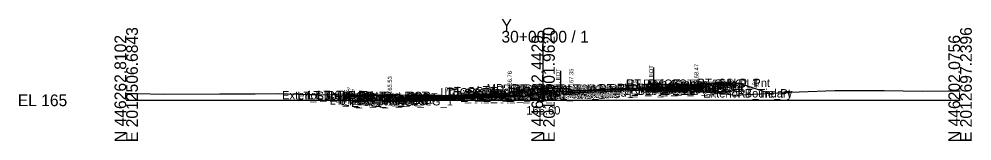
# Model space of a CAD drawing. Extents: x -26 to 3203, y -10 to 9532.
# Drawn here: x 1974.3 to 2202.8, y 3990.3 to 4019.4 of the extents above; entities that cross this region are included whole.
import ezdxf

# ---------------------------------------------------------------- set-up
doc = ezdxf.new("R2010")
doc.units = 0
for name, color, linetype in [('Default', 7, 'Continuous'), ('Exist CMT Pavement', 7, 'Continuous'), ('Exist Cross Section Cell', 7, 'Continuous'), ('Exist XS Center Line Elevation Label', 7, 'Continuous'), ('Exist XS Ground Line', 7, 'Continuous'), ('Prop CMT Conc Surface', 7, 'Continuous'), ('Prop CMT Concrete Structures', 7, 'Continuous'), ('Prop CMT Pvmt Course 1', 7, 'Continuous'), ('Prop CMT Pvmt Course 1 CG', 7, 'Continuous'), ('Prop CMT Pvmt Course 2', 7, 'Continuous'), ('Prop CMT Pvmt Course 2 Wedge', 7, 'Continuous'), ('Prop CMT Pvmt Course 3', 7, 'Continuous'), ('Prop CMT Pvmt Surface', 7, 'Continuous'), ('Prop CMT Pvmt Wedge Surface 2', 7, 'Continuous'), ('Prop CMT Pvmt Wedge Surface 3', 7, 'Continuous'), ('Prop CMT Slope Grass', 7, 'Continuous'), ('Prop CMT Subgrade Earthwork', 7, 'Continuous'), ('Prop XS Hydro Elevations', 7, 'Continuous'), ('Prop XS Label Text', 7, 'Continuous'), ('Prop XS SE Text', 7, 'Continuous'), ('Prop XS Side Slope Text', 7, 'Continuous'), ('Scratch_Level_0', 7, 'Continuous')]:
    doc.layers.add(name, color=color, linetype=linetype)

msp = doc.modelspace()

# ---------------------------------------------------------------- linework, layer by layer
at = {"layer": 'Exist CMT Pavement'}
msp.add_lwpolyline([(2104.17, 4002.07), (2104.17, 4002.07), (2105.31, 4002.11), (2105.93, 4002.14), (2107.94, 4002.25), (2109.92, 4002.32), (2110.57, 4002.34), (2111.82, 4002.38), (2113.18, 4002.43), (2114.04, 4002.47), (2115.35, 4002.53), (2116.08, 4002.56), (2118.4, 4002.63), (2119.51, 4002.66), (2121.03, 4002.71), (2121.82, 4002.73), (2123.64, 4002.76), (2124.34, 4002.78), (2126.48, 4002.84)], dxfattribs=at)
at = {"layer": 'Exist Cross Section Cell'}
for p, q in [((2100, 4000), (2100, 4016.6)), ((2000, 4000), (2100, 4000)), ((2100, 4000), (2200, 4000))]:
    msp.add_line(p, q, dxfattribs=at)
at = {"layer": 'Exist XS Ground Line'}
msp.add_lwpolyline([(2000, 4001.6), (2001.67, 4001.6), (2002.73, 4001.6), (2008.89, 4001.5), (2022.47, 4001.56), (2030.9, 4001.57), (2036.45, 4001.59), (2043.97, 4001.38), (2044.41, 4001.37), (2045.8, 4001.35), (2054.46, 4001.26), (2060.33, 4001.29), (2068.43, 4001.25), (2075.69, 4001.19), (2084.09, 4000.7), (2084.44, 4000.69), (2085.79, 4000.73), (2095.79, 4001.08), (2100, 4001.6), (2101.16, 4001.75), (2102.89, 4001.99), (2103.78, 4002.05), (2104.17, 4002.07), (2105.31, 4002.11), (2105.93, 4002.14), (2107.94, 4002.25), (2109.92, 4002.32), (2110.57, 4002.34), (2111.82, 4002.38), (2113.18, 4002.43), (2114.04, 4002.47), (2115.35, 4002.53), (2116.08, 4002.56), (2118.4, 4002.63), (2119.51, 4002.66), (2121.03, 4002.71), (2121.82, 4002.73), (2123.64, 4002.76), (2124.34, 4002.78), (2126.48, 4002.84), (2127.28, 4002.85), (2127.86, 4002.85), (2128.41, 4002.86), (2130.68, 4002.66), (2134.09, 4002.36), (2136.67, 4002.21), (2143.29, 4001.62), (2145.82, 4001.19), (2155.27, 4001.74), (2157.84, 4001.85), (2161.4, 4001.99), (2169.93, 4002.34), (2177.54, 4002.38), (2180.43, 4002.38), (2181.78, 4002.36), (2190.92, 4002.15), (2197.19, 4002.24), (2200, 4002.29)], dxfattribs=at)
at = {"layer": 'Prop CMT Conc Surface'}
for points in [[(2136.75, 4003.47), (2136.75, 4003.97), (2137.25, 4003.97)], [(2141.25, 4004.06), (2146.25, 4004.16)], [(2091.25, 4001.73), (2092, 4001.76), (2092, 4001.93), (2092.76, 4002.18)], [(2108.75, 4002.43), (2106.75, 4002.35), (2106.75, 4002.52), (2106, 4002.77)], [(2134.75, 4003.47), (2136.75, 4003.47)], [(2058.75, 4001.12), (2053.75, 4001.22)], [(2063.25, 4000.53), (2063.25, 4001.03), (2062.75, 4001.03)], [(2065.25, 4000.69), (2063.25, 4000.53)]]:
    msp.add_lwpolyline(points, dxfattribs=at)
at = {"layer": 'Prop CMT Concrete Structures'}
for points in [[(2134.75, 4003.47), (2136.75, 4003.47), (2136.75, 4003.97), (2137.25, 4003.97)], [(2137.25, 4003.97), (2137.25, 4002.99), (2134.75, 4002.89)], [(2146.25, 4004.16), (2141.25, 4004.06)], [(2141.25, 4004.06), (2141.25, 4003.73)], [(2146.25, 4003.83), (2146.25, 4004.16)], [(2091.25, 4001.73), (2092, 4001.76), (2092, 4001.93), (2092.76, 4002.18)], [(2091.25, 4001.15), (2091.25, 4001.73)], [(2092.76, 4002.18), (2092.76, 4001.21)], [(2108.75, 4002.43), (2106.75, 4002.35), (2106.75, 4002.52), (2106, 4002.77)], [(2106, 4002.77), (2106, 4001.74)], [(2106, 4001.74), (2108.75, 4001.85)], [(2108.75, 4001.85), (2108.75, 4002.43)], [(2134.75, 4002.89), (2134.75, 4003.47)], [(2141.25, 4003.73), (2146.25, 4003.83)], [(2053.75, 4000.89), (2053.75, 4001.22)], [(2053.75, 4001.22), (2058.75, 4001.12)], [(2058.75, 4000.79), (2053.75, 4000.89)], [(2058.75, 4001.12), (2058.75, 4000.79)], [(2065.25, 4000.69), (2063.25, 4000.53), (2063.25, 4001.03), (2062.75, 4001.03)], [(2062.75, 4001.03), (2062.75, 4000.01), (2065.25, 4000.11)], [(2065.25, 4000.11), (2065.25, 4000.69)], [(2092.76, 4001.21), (2091.25, 4001.15)]]:
    msp.add_lwpolyline(points, dxfattribs=at)
at = {"layer": 'Prop CMT Pvmt Course 1'}
for points in [[(2091.25, 4001.73), (2065.25, 4000.69)], [(2091.25, 4001.48), (2091.25, 4001.73)], [(2108.75, 4002.43), (2134.75, 4003.47)], [(2108.75, 4002.18), (2108.75, 4002.43)], [(2108.75, 4002.18), (2108.75, 4002.18)], [(2134.75, 4003.22), (2128.41, 4002.97), (2122.99, 4002.75)], [(2134.75, 4003.47), (2134.75, 4003.22)], [(2065.25, 4000.44), (2091.25, 4001.48)], [(2065.25, 4000.69), (2065.25, 4000.44)], [(2091.25, 4001.48), (2091.25, 4001.48), (2091.25, 4001.48)]]:
    msp.add_lwpolyline(points, dxfattribs=at)
at = {"layer": 'Prop CMT Pvmt Course 1 CG'}
for points in [[(2108.75, 4001.85), (2105.5, 4001.72), (2105.15, 4001.37)], [(2108.75, 4001.52), (2108.75, 4001.85)], [(2134.75, 4002.89), (2137.75, 4003.01), (2138.07, 4002.69)], [(2134.75, 4002.56), (2134.75, 4002.89)], [(2138.07, 4002.69), (2134.75, 4002.56)], [(2065.25, 4000.11), (2062.25, 3999.99), (2061.9, 3999.64)], [(2061.9, 3999.64), (2065.25, 3999.78)], [(2065.25, 3999.78), (2065.25, 4000.11)], [(2091.25, 4001.15), (2093.26, 4001.23), (2093.58, 4000.91)], [(2091.25, 4000.82), (2091.25, 4001.15)], [(2093.58, 4000.91), (2091.25, 4000.82)], [(2105.15, 4001.37), (2108.75, 4001.52)]]:
    msp.add_lwpolyline(points, dxfattribs=at)
at = {"layer": 'Prop CMT Pvmt Course 2'}
msp.add_lwpolyline([(2108.75, 4002.18), (2108.75, 4001.85), (2108.75, 4001.85)], close=True, dxfattribs=at)
for points in [[(2108.75, 4002.18), (2108.75, 4002.18)], [(2126.48, 4002.89), (2134.75, 4003.22)], [(2134.75, 4002.89), (2126.48, 4002.56)], [(2126.48, 4002.56), (2126.48, 4002.89)], [(2134.75, 4003.22), (2134.75, 4002.89)], [(2091.25, 4001.48), (2065.25, 4000.44)], [(2065.25, 4000.11), (2091.25, 4001.15)], [(2065.25, 4000.44), (2065.25, 4000.11)], [(2091.25, 4001.15), (2091.25, 4001.48)]]:
    msp.add_lwpolyline(points, dxfattribs=at)
at = {"layer": 'Prop CMT Pvmt Course 2 Wedge'}
msp.add_lwpolyline([(2122.99, 4002.75), (2126.48, 4002.89)], dxfattribs=at)
at = {"layer": 'Prop CMT Pvmt Course 3'}
for points in [[(2108.75, 4001.85), (2108.75, 4001.85), (2108.75, 4001.52), (2108.75, 4001.52)], [(2108.75, 4001.52), (2108.75, 4001.85)], [(2126.48, 4002.56), (2134.75, 4002.89)], [(2134.75, 4002.56), (2126.48, 4002.22)], [(2126.48, 4002.22), (2126.48, 4002.56)], [(2134.75, 4002.89), (2134.75, 4002.56)], [(2091.25, 4001.15), (2065.25, 4000.11)], [(2065.25, 3999.78), (2091.25, 4000.82)], [(2065.25, 4000.11), (2065.25, 3999.78)], [(2091.25, 4000.82), (2091.25, 4001.15)]]:
    msp.add_lwpolyline(points, dxfattribs=at)
at = {"layer": 'Prop CMT Pvmt Surface'}
for points in [[(2091.25, 4001.73), (2065.25, 4000.69)], [(2108.75, 4002.43), (2134.75, 4003.47)]]:
    msp.add_lwpolyline(points, dxfattribs=at)
at = {"layer": 'Prop CMT Pvmt Wedge Surface 2'}
msp.add_lwpolyline([(2108.75, 4002.18), (2134.75, 4003.22)], dxfattribs=at)
at = {"layer": 'Prop CMT Pvmt Wedge Surface 3'}
msp.add_lwpolyline([(2108.75, 4001.85), (2134.75, 4002.89)], dxfattribs=at)
at = {"layer": 'Prop CMT Slope Grass'}
for points in [[(2137.25, 4003.97), (2146.75, 4004.16)], [(2146.75, 4004.16), (2154.22, 4001.67)], [(2092.76, 4002.18), (2099.38, 4002.9)], [(2106, 4002.77), (2099.38, 4002.9)], [(2053.25, 4001.22), (2053.11, 4001.27)], [(2062.75, 4001.03), (2053.25, 4001.22)]]:
    msp.add_lwpolyline(points, dxfattribs=at)
at = {"layer": 'Prop CMT Subgrade Earthwork'}
for points in [[(2134.75, 4002.56), (2138.07, 4002.69), (2139.4, 4004.02)], [(2095.11, 4002.44), (2093.58, 4000.91)], [(2103.71, 4002.81), (2105.15, 4001.37)], [(2108.75, 4001.52), (2108.74, 4002.27)], [(2126.48, 4002.22), (2126.5, 4002.84)], [(2126.48, 4002.22), (2134.75, 4002.56)], [(2134.75, 4002.56), (2134.75, 4002.56)], [(2065.25, 3999.78), (2061.9, 3999.64), (2060.47, 4001.08)], [(2091.25, 4000.82), (2065.25, 3999.78)], [(2065.25, 3999.78), (2065.25, 3999.78)], [(2093.58, 4000.91), (2091.25, 4000.82)], [(2091.25, 4000.82), (2091.25, 4000.82)], [(2091.25, 4000.82), (2091.25, 4000.82)], [(2105.15, 4001.37), (2108.75, 4001.52)], [(2108.75, 4001.52), (2108.75, 4001.52)], [(2108.75, 4001.52), (2108.75, 4001.52)]]:
    msp.add_lwpolyline(points, dxfattribs=at)
at = {"layer": 'Prop XS Label Text'}
for p, q in [((2104.17, 4007.07), (2104.17, 4002.07)), ((2126.48, 4007.84), (2126.48, 4002.84))]:
    msp.add_line(p, q, dxfattribs=at)

# ---------------------------------------------------------------- texts
at = {"layer": 'Default'}
msp.add_text('-', height=0.0001, dxfattribs=at).set_placement((2000, 4000))
at = {"layer": 'Exist Cross Section Cell'}
for s, p in [('Y', (2090, 4016.6)), ('30+00.00 / 1', (2090, 4013.8)), ('EL 165', (1974, 3998.6))]:
    msp.add_text(s, height=2.8, dxfattribs=at).set_placement(p)
for s, p in [('N 446262.8102', (2000, 3990)), ('E 2012506.6843', (2002.8, 3990)), ('N 446232.4429', (2100, 3990)), ('E 2012601.9620', (2102.8, 3990)), ('N 446202.0756', (2200, 3990)), ('E 2012697.2396', (2202.8, 3990))]:
    msp.add_text(s, height=2.8, rotation=90, dxfattribs=at).set_placement(p)
at = {"layer": 'Exist XS Center Line Elevation Label'}
msp.add_text('166.60', height=2, dxfattribs=at).set_placement((2095.95, 3996.6))
at = {"layer": 'Prop XS Hydro Elevations'}
for s, p in [('168.47', (2137.25, 4004.47)), ('166.76', (2092.5, 4002.76)), ('167.35', (2107.25, 4003.35)), ('165.53', (2063.75, 4001.53))]:
    msp.add_text(s, height=1, rotation=90, dxfattribs=at).set_placement(p)
at = {"layer": 'Prop XS Label Text'}
for p in [(2104.07, 4003.09), (2126.38, 4003.86)]:
    msp.add_text('E. EOT', height=1, rotation=90, dxfattribs=at).set_placement(p)
at = {"layer": 'Prop XS SE Text'}
for p in [(2119.96, 4003.88), (2076.46, 4002.14)]:
    msp.add_text('0.040', height=1, rotation=2.2906, dxfattribs=at).set_placement(p)
at = {"layer": 'Prop XS Side Slope Text'}
for p in [(2149.97, 4003.88), (2052.66, 4002.21)]:
    msp.add_text('3:1', height=1, rotation=341.5651, dxfattribs=at).set_placement(p)
at = {"layer": 'Scratch_Level_0'}
for s, p in [('MD_Crown Point', (2086.45, 4001.9)), ('RT_Sub_DLT_In', (2092.61, 4001.81)), ('RT_PV_Sub_Tie_Out', (2113.32, 4001.86)), ('RT_PV_OEEOP_EG', (2115.91, 4001.86)), ('RT_PV2_OEEOP', (2117.67, 4001.97)), ('RT_Sub_Trench_Out_DLT', (2119.92, 4003.02)), ('RT_CG_Top_Face', (2123.96, 4002.97)), ('RT_CG1_Shelf_Out', (2124.25, 4002.01)), ('RT_CG_Bot_IE', (2124.62, 4001.89)), ('RT_PV2_OEOT', (2124.88, 4002.22)), ('RT_PV3_OEOT', (2124.88, 4001.89)), ('RT_CG_Top_Gut', (2124.94, 4002.47)), ('RT_PV1_OEOT', (2125.44, 4002.47)), ('RT_CG_Top_BOC', (2125.49, 4002.97)), ('RT_CG_Bot_BOC', (2125.52, 4001.99)), ('RT_CSLP_Pnt', (2136.88, 4003.16)), ('Exterior Boundary', (2037.39, 4000.22)), ('LT_Sub_Trench_Out_DLT', (2041.03, 4000.08)), ('LT_CSLP_Pnt', (2043.42, 4000.22)), ('LT_Tie_Pt', (2045.82, 4000.27)), ('LT_CG_Top_Face', (2050.51, 4000.03)), ('LT_CG_Top_BOC', (2051.03, 4000.03)), ('LT_PV1_OEOT', (2055.99, 3999.69)), ('LT_CG_Top_Face_Med', (2075.37, 4000.93)), ('LT_CG_Top_Gut_Med', (2076.35, 4000.76)), ('LT_CG_Top_BOC_Med', (2077.15, 4001.18)), ('LT_CG_Bot_BOC_Med', (2077.19, 4000.21)), ('LT_CG_Bot_IE_Med', (2077.31, 4000.15)), ('LT_Sub_IEOT_CG_1', (2078.12, 3999.82)), ('LT_Sub_OEEOP', (2080.46, 3999.82)), ('LT_PV2_OEEOP', (2080.56, 4000.48)), ('LT_PV3_OEEOP', (2080.56, 4000.15)), ('LT_Sub_IEEOP', (2081.11, 3999.82)), ('LT_PV2_IEEOP', (2081.2, 4000.48)), ('LT_CG1_Shelf_In', (2081.43, 4000.23)), ('LT_Sub_PGL', (2082.37, 3999.82)), ('LT_PV2_PGL', (2082.46, 4000.48)), ('LT_PV1_PGL', (2083.03, 4000.73)), ('LT_Sub_DLT_In', (2084.05, 4001.44)), ('LT_Sub_IEOP', (2084.34, 3999.91)), ('RT_CG_Top_BOC_Med', (2090.35, 4001.77)), ('RT_CG_Bot BOC In', (2091.84, 4000.74)), ('RT_CG_Top_BOC In', (2091.97, 4001.77)), ('RT_CG_Top FOC In', (2092.61, 4001.52)), ('RT_CG_Top_Gut In', (2092.64, 4001.35)), ('RT_CG1_Shelf_In', (2093.63, 4000.72)), ('RT_CG_Bot_IE_Med', (2094.77, 4000.85)), ('RT_PV_Sub_Tie_In', (2095.25, 4001.27)), ('RT_Sub_IEOT_CG_1', (2095.57, 4000.52)), ('RT_Sub_IEOP', (2095.86, 4000.37)), ('RT_PV_IEEOP_EG', (2096.89, 4001.28)), ('RT_Sub_IEEOP', (2098.56, 4000.52)), ('RT_PV2_IEEOP', (2098.66, 4001.18)), ('RT_PV3_IEEOP', (2098.66, 4000.85)), ('RT_Sub_PGL', (2099.82, 4000.52)), ('RT_PV2_PGL', (2099.92, 4001.18)), ('RT_PV3_PGL', (2099.92, 4000.85)), ('RT_PV1_PGL', (2100.48, 4001.43)), ('RT_Sub_OEEOP', (2117.58, 4001.3)), ('RT_PV3_OEEOP', (2117.67, 4001.64)), ('RT_Sub_OEOT_CG_1', (2120.92, 4001.56)), ('RT_Sub_OEOT', (2124.78, 4001.56)), ('RT_Sub_OEOP', (2128.13, 4001.69)), ('Exterior Boundary', (2138.36, 4000.67)), ('RT_Tie_Pt', (2146.61, 4000.67)), ('LT_CG1_Shelf_Out', (2048.8, 3998.99)), ('LT_CG_Bot_BOC', (2051.06, 3999.01)), ('LT_Sub_OEOT_CG_1', (2051.47, 3998.78)), ('LT_CG_Top_Gut', (2051.49, 3999.53)), ('LT_Sub_OEOP', (2052.01, 3998.64)), ('LT_CG_Bot_IE', (2055.16, 3999.11)), ('LT_Sub_OEOT', (2055.33, 3998.78)), ('LT_PV2_OEOT', (2055.42, 3999.44)), ('LT_PV3_OEOT', (2055.42, 3999.11))]:
    msp.add_text(s, height=2, dxfattribs=at).set_placement(p)

doc.saveas('drawing.dxf')
